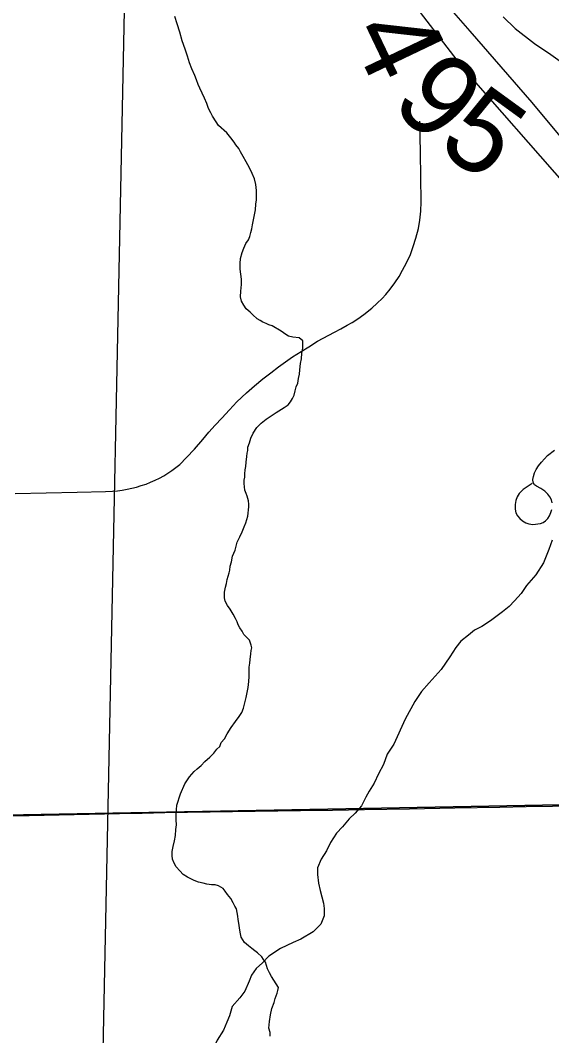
# Model space of a CAD drawing. Extents: x -6.1 to 38, y -7.7 to 22.
# Drawn here: x 3.241 to 3.606, y 19.227 to 19.926 of the extents above; entities that cross this region are included whole.
import ezdxf

# ---------------------------------------------------------------- set-up
doc = ezdxf.new("R2010")
doc.units = 0
for name, color, linetype in [('GM_X_Corporation', 7, 'Continuous'), ('GM_X_County_Road', 7, 'Continuous'), ('GM_X_County_Road_Text', 7, 'Continuous'), ('GM_X_Minor_River', 7, 'Continuous'), ('GM_X_Rail_Line', 7, 'Continuous'), ('GM_X_Township_Road', 7, 'Continuous'), ('GM_X_US_Route', 7, 'Continuous')]:
    doc.layers.add(name, color=color, linetype=linetype)

msp = doc.modelspace()

# ---------------------------------------------------------------- linework, layer by layer
at = {"layer": 'GM_X_Corporation'}
for points in [[(6.96628, 20.9), (2.1, 20.9), (2.1, 19.36551), (3.07052, 19.37611), (3.09907, 19.37662), (3.10966, 19.37681), (3.12026, 19.377), (3.14426, 19.37751), (3.74766, 19.38857), (3.77587, 19.3894), (3.92442, 19.39221), (3.97926, 19.39329), (4.02764, 19.39424), (4.10065, 19.39567), (4.15155, 19.39684), (4.22089, 19.39843), (4.27649, 19.3997)], [(4.27649, 19.3997), (4.22089, 19.39843), (4.15155, 19.39684), (4.10065, 19.39567), (4.02764, 19.39424), (3.97926, 19.39329), (3.92442, 19.39221), (3.77587, 19.3894), (3.74766, 19.38857), (3.14426, 19.37751), (3.12026, 19.377), (3.10966, 19.37681), (3.09907, 19.37662), (3.07052, 19.37611), (2.1, 19.36551), (2.1, 14.52316)]]:
    msp.add_lwpolyline(points, dxfattribs=at)
msp.add_lwpolyline([(2.34542, 20.09827), (2.41961, 20.09248), (2.47052, 20.0902), (2.61883, 20.08595), (2.79073, 20.08068), (2.90281, 20.07752), (3.06866, 20.07303), (3.29109, 20.06779), (3.31497, 20.0668), (3.29694, 19.18347), (3.29403, 19.05339), (2.3594, 19.07674)], close=True, dxfattribs=at)
at = {"layer": 'GM_X_County_Road'}
for points in [[(3.57266, 19.92809), (3.58102, 19.92004), (3.59431, 19.90978), (3.6054, 19.90225), (3.62817, 19.88592)], [(3.21579, 19.37825), (3.24685, 19.37889), (3.27791, 19.37953), (3.30898, 19.38017), (3.32459, 19.38049), (3.34021, 19.38081), (3.37127, 19.38127), (3.40233, 19.38175), (3.43339, 19.38221), (3.45537, 19.38254), (3.47734, 19.38288), (3.5084, 19.38345), (3.53946, 19.38401), (3.57052, 19.38459), (3.58854, 19.38491), (3.60656, 19.38524), (3.63763, 19.38576), (3.66869, 19.38628), (3.69144, 19.38665), (3.71418, 19.38703), (3.73095, 19.38742), (3.74773, 19.3878), (3.76238, 19.38813), (3.77678, 19.38844)]]:
    msp.add_lwpolyline(points, dxfattribs=at)
at = {"layer": 'GM_X_Minor_River'}
for points in [[(3.39212, 19.83516), (3.39095, 19.83743), (3.38902, 19.84007), (3.38786, 19.84196), (3.38554, 19.84497), (3.38284, 19.84837), (3.37708, 19.85326), (3.37553, 19.8559), (3.37282, 19.85968), (3.37166, 19.86195), (3.3701, 19.86497), (3.36892, 19.86838), (3.36736, 19.87217), (3.3658, 19.87558), (3.36424, 19.87898), (3.36307, 19.88163), (3.36189, 19.88466), (3.36072, 19.88769), (3.35876, 19.89224), (3.35719, 19.8964), (3.35562, 19.90095), (3.35404, 19.90588), (3.35207, 19.91156), (3.35048, 19.91763), (3.34852, 19.92331), (3.34694, 19.92824)], [(3.38482, 19.54763), (3.38516, 19.55029), (3.38589, 19.55334), (3.38661, 19.55715), (3.38846, 19.56135), (3.38992, 19.56669), (3.39177, 19.57051), (3.39325, 19.57395), (3.39473, 19.57739), (3.39584, 19.58006), (3.39658, 19.58235), (3.39731, 19.58464), (3.398, 19.59111), (3.39797, 19.59301), (3.39757, 19.59529), (3.39677, 19.59832), (3.39599, 19.60021), (3.3952, 19.60249), (3.3948, 19.60476), (3.39477, 19.60704), (3.39474, 19.60933), (3.3951, 19.61161), (3.39507, 19.61389), (3.39542, 19.61656), (3.39577, 19.61884), (3.39612, 19.62189), (3.39645, 19.62569), (3.39681, 19.62798), (3.39716, 19.62988), (3.39714, 19.63216), (3.39824, 19.63522), (3.39935, 19.63827), (3.40083, 19.64171), (3.40345, 19.64554), (3.40645, 19.64861), (3.40984, 19.6513), (3.41324, 19.65362), (3.41663, 19.65593), (3.42229, 19.65941), (3.42493, 19.66134), (3.42643, 19.66326), (3.42792, 19.66555), (3.42904, 19.66784), (3.42976, 19.67089), (3.43049, 19.67356), (3.4316, 19.67623), (3.43195, 19.67928), (3.43267, 19.68233), (3.43302, 19.68537), (3.43335, 19.68956), (3.43407, 19.69299), (3.4344, 19.69679), (3.43512, 19.70022), (3.43509, 19.70327), (3.43507, 19.70517), (3.43238, 19.70742), (3.42819, 19.70776), (3.42515, 19.70849), (3.42323, 19.70961), (3.42016, 19.71186), (3.41404, 19.7156), (3.41175, 19.71634), (3.40984, 19.71708), (3.40754, 19.7182), (3.40563, 19.71932), (3.40372, 19.72044), (3.40064, 19.72308), (3.39872, 19.72496), (3.39603, 19.72721), (3.39448, 19.72986), (3.39293, 19.7325), (3.39213, 19.73554), (3.39247, 19.73934), (3.3928, 19.74391), (3.39275, 19.74771), (3.39233, 19.75113), (3.39191, 19.75454), (3.39187, 19.75835), (3.39221, 19.76177), (3.3933, 19.76597), (3.39441, 19.76902), (3.39589, 19.77208), (3.39776, 19.77476), (3.3985, 19.77704), (3.39922, 19.77971), (3.39995, 19.78238), (3.4003, 19.78505), (3.40102, 19.78848), (3.40175, 19.79191), (3.40247, 19.79533), (3.4028, 19.79914), (3.40315, 19.80219), (3.40311, 19.80523), (3.40307, 19.80865), (3.40264, 19.81283), (3.40184, 19.81662), (3.40027, 19.82041), (3.39833, 19.82419), (3.396, 19.82835), (3.39405, 19.83213), (3.39212, 19.83516)], [(3.60643, 19.56824), (3.60419, 19.56178), (3.60045, 19.55267), (3.5952, 19.54431), (3.58881, 19.53708), (3.58506, 19.53138), (3.58055, 19.52643), (3.57679, 19.52263), (3.57227, 19.51882), (3.56399, 19.51272), (3.55797, 19.50891), (3.55307, 19.50623), (3.54893, 19.5028), (3.54365, 19.49861), (3.54028, 19.49443), (3.53615, 19.48797), (3.53014, 19.47923), (3.52187, 19.47009), (3.51661, 19.46401), (3.51211, 19.45717), (3.50537, 19.44501), (3.49752, 19.42792), (3.49301, 19.42108), (3.4904, 19.41387), (3.48703, 19.40741), (3.48404, 19.40095), (3.48066, 19.39563), (3.47842, 19.39146), (3.47542, 19.38538), (3.47091, 19.38043), (3.46678, 19.37663), (3.46227, 19.37092), (3.45813, 19.36674), (3.45401, 19.36027), (3.45139, 19.35458), (3.44764, 19.34888), (3.44502, 19.3428), (3.44504, 19.33825), (3.44583, 19.33219), (3.44698, 19.32727), (3.44929, 19.31856), (3.44969, 19.31477), (3.44971, 19.30985), (3.44747, 19.30415), (3.44221, 19.29882), (3.43354, 19.29386), (3.42826, 19.29156), (3.41959, 19.28736), (3.41168, 19.28202), (3.40717, 19.27745), (3.40303, 19.27364), (3.39965, 19.26908), (3.39816, 19.26491), (3.39517, 19.25807)], [(3.41664, 19.26313), (3.41354, 19.26804), (3.41199, 19.27069), (3.41081, 19.27334), (3.41003, 19.27562), (3.40924, 19.27789), (3.40808, 19.27978), (3.40692, 19.28167), (3.40385, 19.2843), (3.40193, 19.2858), (3.40001, 19.2873), (3.39771, 19.28919), (3.39502, 19.29144), (3.39269, 19.29522), (3.39189, 19.29863), (3.39148, 19.30167), (3.39106, 19.30471), (3.39065, 19.30737), (3.39024, 19.30964), (3.38943, 19.31458), (3.38826, 19.31647), (3.3871, 19.31874), (3.38554, 19.32177), (3.38323, 19.3244), (3.38168, 19.32667), (3.38014, 19.32856), (3.37708, 19.33043), (3.37479, 19.33117), (3.37213, 19.33114), (3.36908, 19.33149), (3.36641, 19.33222), (3.36336, 19.33295), (3.36031, 19.33406), (3.35572, 19.3363), (3.35266, 19.33817), (3.35034, 19.34081), (3.34803, 19.34345), (3.34648, 19.34609), (3.34531, 19.34874), (3.34528, 19.3514), (3.34525, 19.35407), (3.34597, 19.3575), (3.34668, 19.3613), (3.3474, 19.36512), (3.34773, 19.3693), (3.34808, 19.37235), (3.34804, 19.37577), (3.34799, 19.37957), (3.3483, 19.38604), (3.35087, 19.39367), (3.35383, 19.40054), (3.35719, 19.40552), (3.3602, 19.40897), (3.36246, 19.4109), (3.36509, 19.4132), (3.36772, 19.41589), (3.37111, 19.41897), (3.37373, 19.42165), (3.37598, 19.42434), (3.37786, 19.42626), (3.37897, 19.42893), (3.38122, 19.43162), (3.38308, 19.43506), (3.3857, 19.43927), (3.38869, 19.44348), (3.39131, 19.44693), (3.39318, 19.44961), (3.39428, 19.45266), (3.3961, 19.4599), (3.39682, 19.46333), (3.39754, 19.46676), (3.39787, 19.47095), (3.39821, 19.47437), (3.39817, 19.47779), (3.39814, 19.48084), (3.39849, 19.4835), (3.39883, 19.48617), (3.39917, 19.48997), (3.39953, 19.49226), (3.39988, 19.49416), (3.39948, 19.49606), (3.3983, 19.49947), (3.39638, 19.50135), (3.39446, 19.50323), (3.39329, 19.50551), (3.39174, 19.50777), (3.39057, 19.51004), (3.38979, 19.51194), (3.38862, 19.5142), (3.38707, 19.51723), (3.38513, 19.52063), (3.3832, 19.52328), (3.38164, 19.5263), (3.38123, 19.52858), (3.38119, 19.53238), (3.38191, 19.53581), (3.38264, 19.53848), (3.38299, 19.54115), (3.38372, 19.54343), (3.38446, 19.54572), (3.38482, 19.54763)], [(3.4125, 19.22697), (3.41246, 19.22963), (3.41167, 19.23266), (3.412, 19.23723), (3.4127, 19.2418), (3.41379, 19.24599), (3.41526, 19.25019), (3.41599, 19.25286), (3.41673, 19.25477), (3.41747, 19.25668), (3.41783, 19.25858), (3.41819, 19.26049), (3.41664, 19.26313)], [(3.39517, 19.25807), (3.39179, 19.25351), (3.38653, 19.24742), (3.38467, 19.24097), (3.3828, 19.2368), (3.38057, 19.2311), (3.37606, 19.22426), (3.37195, 19.21591), (3.36819, 19.21021), (3.3622, 19.19995), (3.35619, 19.19272), (3.35093, 19.18701)]]:
    msp.add_lwpolyline(points, dxfattribs=at)
at = {"layer": 'GM_X_Rail_Line'}
msp.add_lwpolyline([(2.1, 20.22672), (2.72238, 19.85623), (2.78818, 19.82405), (2.83715, 19.81025), (2.88459, 19.81024), (2.93803, 19.82546), (2.99132, 19.87524), (3.04538, 19.90505), (3.0964, 19.92627), (3.15298, 19.92829), (3.20022, 19.92551), (3.24316, 19.93561), (3.30555, 19.95557), (3.37905, 19.97249), (3.43412, 19.97653), (3.46898, 19.97552), (3.495, 19.95808), (3.54553, 19.89238), (3.61618, 19.81161), (3.7762, 19.63742), (3.82168, 19.57425), (3.97265, 19.2587), (4.0109, 19.20357)], dxfattribs=at)
at = {"layer": 'GM_X_Township_Road'}
for points in [[(3.23734, 19.60029), (3.25855, 19.60072), (3.27977, 19.60114), (3.29933, 19.60164), (3.30416, 19.60187), (3.30753, 19.60215), (3.31085, 19.60257), (3.31421, 19.60313), (3.31748, 19.60384), (3.32075, 19.60468), (3.32397, 19.60566), (3.3272, 19.60677), (3.33032, 19.60802), (3.3334, 19.60939), (3.33639, 19.61089), (3.33937, 19.61252), (3.34226, 19.61427), (3.34506, 19.61614), (3.34776, 19.61812), (3.35042, 19.62023), (3.35509, 19.62502), (3.36051, 19.63082), (3.36625, 19.63735), (3.37047, 19.64235), (3.37479, 19.64724), (3.37924, 19.65205), (3.38455, 19.65782), (3.38974, 19.66324), (3.39627, 19.66953), (3.40182, 19.67434), (3.40761, 19.67903), (3.41291, 19.68322), (3.41834, 19.68741), (3.42796, 19.69432), (3.43388, 19.69789), (3.43918, 19.70122), (3.4451, 19.70492), (3.45674, 19.71116), (3.46108, 19.71351), (3.4656, 19.71596), (3.46897, 19.71794), (3.47278, 19.72042), (3.47691, 19.72342), (3.48248, 19.72783), (3.48617, 19.73118), (3.48946, 19.73442), (3.49206, 19.73723), (3.49497, 19.74071), (3.49824, 19.74512), (3.50114, 19.7496), (3.50358, 19.7538), (3.50638, 19.75893), (3.50897, 19.7646), (3.51097, 19.77005), (3.51279, 19.77582), (3.51452, 19.7826), (3.5155, 19.78815), (3.51612, 19.79432), (3.51636, 19.80085), (3.51612, 19.81787), (3.51587, 19.83488), (3.5155, 19.85634)], [(3.60644, 19.59386), (3.60589, 19.59593), (3.60485, 19.59794), (3.60339, 19.59989), (3.60147, 19.60195), (3.59861, 19.60377), (3.5957, 19.6053), (3.59431, 19.60627), (3.59327, 19.60779), (3.5932, 19.60988), (3.59348, 19.61196), (3.59431, 19.61439), (3.59535, 19.61681), (3.59696, 19.61935), (3.59917, 19.62192), (3.60332, 19.6263), (3.60813, 19.63)], [(3.59258, 19.60724), (3.58655, 19.60295), (3.58383, 19.60031), (3.58238, 19.59808), (3.58134, 19.59545), (3.58088, 19.59273), (3.58096, 19.58948), (3.58147, 19.58708), (3.58266, 19.58483), (3.58412, 19.58298), (3.586, 19.58139), (3.58834, 19.58005), (3.59044, 19.57931), (3.59313, 19.57901), (3.59833, 19.57956), (3.60034, 19.5804), (3.6018, 19.58152), (3.60333, 19.58296), (3.60452, 19.58484), (3.60557, 19.58721), (3.60624, 19.58935)]]:
    msp.add_lwpolyline(points, dxfattribs=at)
at = {"layer": 'GM_X_US_Route'}
msp.add_lwpolyline([(3.52742, 19.94405), (3.54971, 19.91826), (3.59233, 19.86908), (3.62971, 19.82428), (3.66249, 19.78647), (3.73877, 19.69707), (3.77236, 19.65718), (3.78708, 19.63937), (3.80303, 19.61839), (3.81329, 19.60263), (3.82397, 19.58555), (3.83159, 19.57365), (3.85332, 19.53273), (3.86226, 19.51478), (3.87072, 19.49655)], dxfattribs=at)

# ---------------------------------------------------------------- texts
at = {"layer": 'GM_X_County_Road_Text'}
for s, rotation, p in [('4', 295.54472, (3.46612, 19.91727)), ('9', 316.34193, (3.49435, 19.86756)), ('5', 323.95257, (3.526, 19.83812))]:
    msp.add_text(s, height=0.05682, rotation=rotation, dxfattribs=at).set_placement(p)

doc.saveas('drawing.dxf')
